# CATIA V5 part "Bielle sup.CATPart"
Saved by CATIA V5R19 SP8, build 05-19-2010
Part number: Bielle sup
Bounding box of the stored display mesh (mm): x 75 to 425, y -30 to 30, z -24.818 to 24.818
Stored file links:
  C:\Users\ThinkMotion\Desktop\EU_thinkMotion\iao\IAO_MMS_Groupe3\rdalborgo\rdalborgo\Bielle sup.CATPart
  C:\Users\ThinkMotion\Desktop\EU_thinkMotion\iao\IAO_MMS_Groupe3\rdalborgo\rdalborgo\rdalborgo.CATProduct
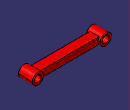
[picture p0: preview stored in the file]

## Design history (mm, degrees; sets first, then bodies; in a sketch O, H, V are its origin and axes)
External parameters (linked from other documents)
  `External.Axe inter diam` = 30 mm
  `External.Axe exter diam` = 50 mm
  `External.Longueur bielle` = 300 mm
  `External.Demi hauteur bielle` = 15 mm
  `External.Demi epaisseur bielle` = 20 mm
  `External.Demi epaisseur tete bielle` = 30 mm
Set1
  Plane1: linked copy from another document
  Point1 "A bielle": linked copy from another document
  Point2 "B bielle": linked copy from another document
  Line1: linked copy from another document
Body1 (main body)
  Sketch1 on Plane1, origin (0, 0, 0), H (-1, 0, 0), V (0, 0, 1)
    circle A1 centre (-100, 0) radius 25
    point P1 (-100, 0)
    circle A2 centre (-100, 0) radius 15
    point P2 (-100, 0)
    reference projected point E1 (-100, 0) from Point1
    circle A3 centre (-400, 0) radius 25
    point P3 (-400, 0)
    circle A4 centre (-400, 0) radius 15
    reference projected point E2 (-400, 0) from Point2
    radius A1 = 25 {= `External.Axe exter diam` /2}
    radius A2 = 15 {= `External.Axe inter diam` /2}
    radius A4 = 15 {= `External.Axe inter diam` /2}
    radius A3 = 25 {= `External.Axe exter diam` /2}
    coincidence: P2 P1, P2 E1, P3 E2
  Pad1: profile Sketch1, direction (0, 1, 0), length 30 {= `External.Demi epaisseur tete bielle`}, mirrored extent
  Sketch2 on Plane1, origin (0, 0, 0), H (-1, 0, 0), V (0, 0, 1)
    line L1 (-385, 15) -> (-115, 15)
    line L2 (-115, 15) -> (-115, -15)
    line L3 (-115, -15) -> (-385, -15)
    line L4 (-385, -15) -> (-385, 15)
    reference projected point E1 (-100, 0) from Point1
    reference projected line E2 (-100, 0) -> (-400, 0) from Line1
    reference projected line E3 (-100, 0) -> (-400, 0) from Line1
    distance L4 L2 = 270 {= `External.Longueur bielle` -`External.Axe inter diam`}
    distance L2 E1 = 15 {= `External.Axe inter diam` /2}
    distance L1 E2 = 15 {= `External.Demi hauteur bielle`}
    distance L3 E3 = 15 {= `External.Demi hauteur bielle`}
    horizontal: L1 H, L3 H
    vertical: L2 V, L4 V
  Pad2: profile Sketch2, direction (0, 1, 0), length 20 {= `External.Demi epaisseur bielle`}, mirrored extent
